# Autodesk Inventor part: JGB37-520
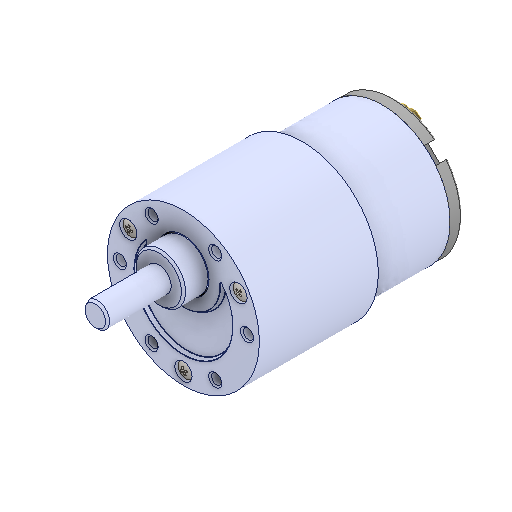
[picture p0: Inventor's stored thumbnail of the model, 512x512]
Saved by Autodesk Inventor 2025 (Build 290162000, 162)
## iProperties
Created: 2017-03
Part Number: JGB37-520
Material: Generico
Description: STEP AP214
Document SubType Name: Modeling
Designer: R5800u
Density: 1 g/cm^3
Appearance: Default
Sending System: SolidWorks 2017
Preprocessor: SwSTEP 2.0
Title: JGB37-520.STEP
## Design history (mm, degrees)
feature "GEARED BODY, MOTOR, JGB37-520_1:1"
feature "DC MOTOR, JGB37-520_2:1"
feature "MOTOR SHAFT, JGB37-520_3:1"
feature "SHAFT COUPLER, JGB37-520_4:1"
feature "COUPLING BRACKET, GEARED BODY TO DC MOTOR, JGB37-520_5:1"
feature "PLASTIC COVER, DC MOTOR, JGB37-520_6:1"
feature "CONNECTION, DC MOTOR, JGB37-520_7:1"
feature "CONNECTION, DC MOTOR, JGB37-520_8:1"
feature "pan cross head_am_B18.6.7M - M2 x 0.4 x 25 Type I Cross Rece"
node "Solido1"
node "Solido2"
node "Solido3"
node "Solido4"
node "Solido5"
node "Solido6"
node "Solido7"
node "Solido8"
node "Solido9"
node "Solido10"
node "Solido11"
